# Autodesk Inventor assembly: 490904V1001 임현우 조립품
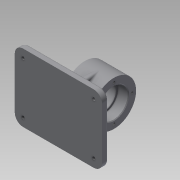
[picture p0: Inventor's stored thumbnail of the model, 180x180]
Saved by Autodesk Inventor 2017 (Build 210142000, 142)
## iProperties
Part Number: 490904V1001 임현우 조립품
Material: 일반
Document SubType Name: Assembly
Designer: 603-17
Author: 603-17
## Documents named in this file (2)
- C:\Users\603-17\Desktop\490904V1001\490904V1001 임현우 조립품.iam
- C:\Users\603-17\Desktop\490904V1001\490904V1001 임현우.ipt
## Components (1 placed, 1 different names)
1. 490904V1001 임현우:1
